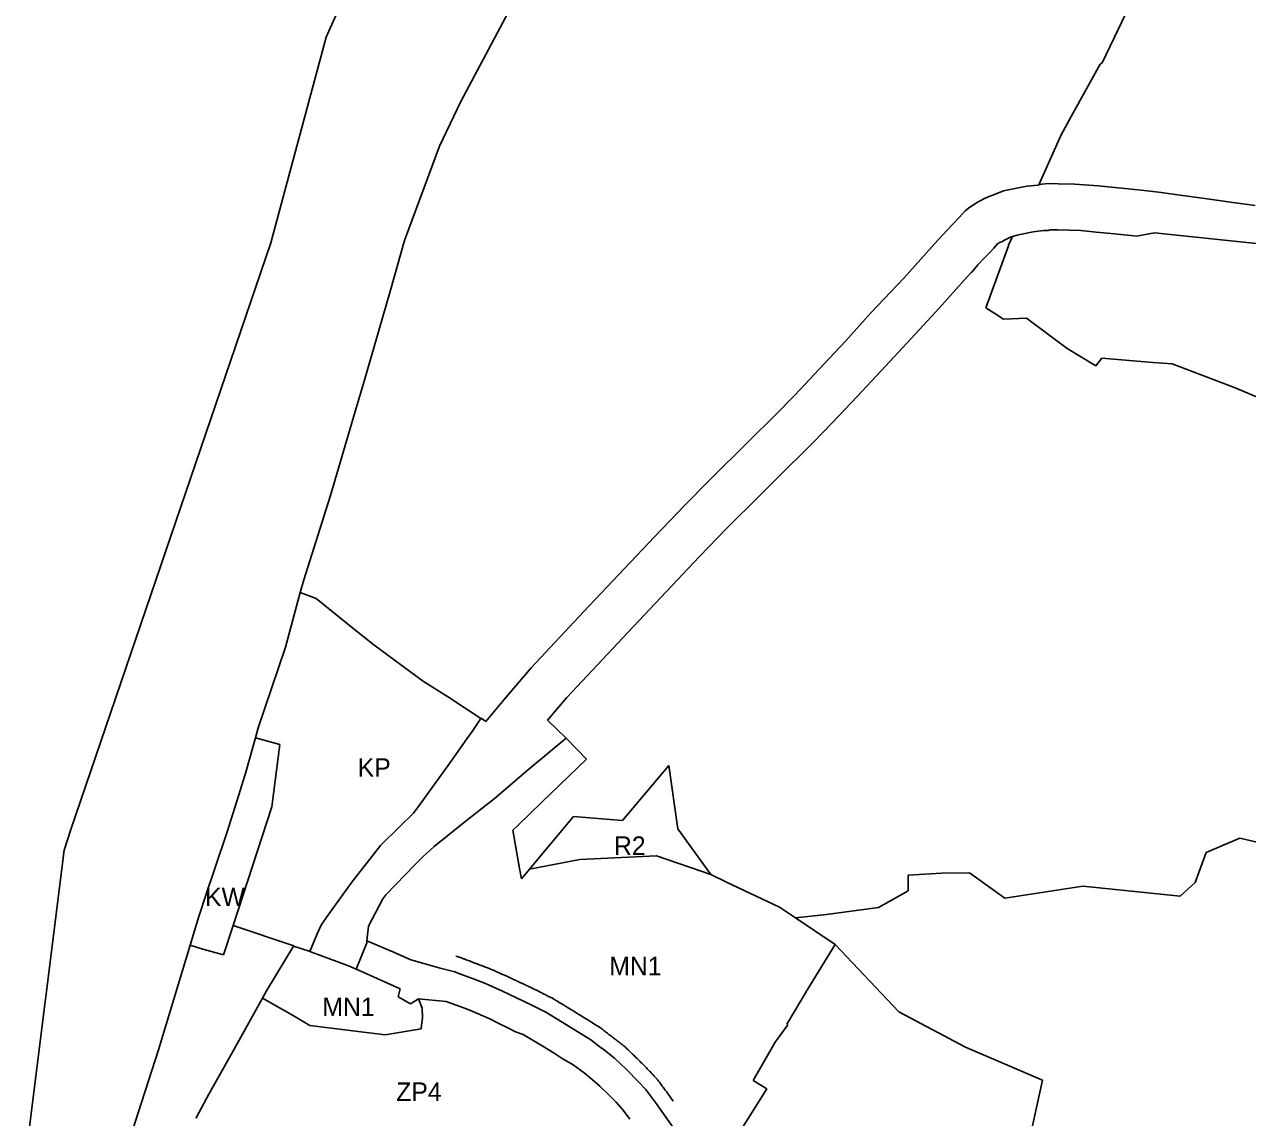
# Model space of a CAD drawing. Extents: x 7413438 to 7416393, y 5541665 to 5544118.
# Drawn here: x 7414058.8 to 7414455.4, y 5543282 to 5543636.5 of the extents above; entities that cross this region are included whole.
import ezdxf

# ---------------------------------------------------------------- set-up
doc = ezdxf.new("R2010")
doc.units = 0
for name, color, linetype in [('linie_rozgraniczajace', 7, 'Continuous'), ('linie_zabudowy_nieprzekraczalne', 7, 'Continuous'), ('oznaczenia_przeznaczen', 7, 'Continuous')]:
    doc.layers.add(name, color=color, linetype=linetype)

msp = doc.modelspace()

# ---------------------------------------------------------------- linework, layer by layer
at = {"layer": 'linie_rozgraniczajace'}
for p, q in [((7414156.63, 5543632.35), (7414203.36, 5543738.15)), ((7414423.99, 5543656.83), (7414408.2, 5543624.04)), ((7414220.77, 5543650.15), (7414200.34, 5543611.48)), ((7414138.74, 5543565.69), (7414156.63, 5543632.35)), ((7414407.58, 5543623.65), (7414398.23, 5543606.68)), ((7414408.2, 5543624.04), (7414407.58, 5543623.65)), ((7414200.34, 5543611.48), (7414193.34, 5543597.07)), ((7414398.23, 5543606.68), (7414394.97, 5543600.71)), ((7414394.97, 5543600.71), (7414387.68, 5543584.53)), ((7414193.34, 5543597.07), (7414182.06, 5543566.46)), ((7414380.6, 5543583.43), (7414376.29, 5543582.54)), ((7414383.79, 5543584.09), (7414380.6, 5543583.43)), ((7414387.64, 5543584.44), (7414383.79, 5543584.09)), ((7414387.68, 5543584.53), (7414387.64, 5543584.44)), ((7414387.68, 5543584.53), (7414387.69, 5543584.49)), ((7414387.69, 5543584.49), (7414388.73, 5543584.76)), ((7414388.73, 5543584.76), (7414390.91, 5543584.95)), ((7414390.91, 5543584.95), (7414393.95, 5543584.87)), ((7414393.95, 5543584.87), (7414399.43, 5543584.71)), ((7414399.43, 5543584.71), (7414406.96, 5543584.2)), ((7414406.96, 5543584.2), (7414413.4, 5543583.54)), ((7414413.4, 5543583.54), (7414420.86, 5543582.78)), ((7414420.86, 5543582.78), (7414426.64, 5543582.14)), ((7414368.03, 5543578.98), (7414365.32, 5543577.23)), ((7414370.48, 5543580.34), (7414368.03, 5543578.98)), ((7414374.43, 5543581.84), (7414370.48, 5543580.34)), ((7414376.29, 5543582.54), (7414374.43, 5543581.84)), ((7414426.64, 5543582.14), (7414432.69, 5543581.29)), ((7414432.69, 5543581.29), (7414435.2, 5543580.95)), ((7414435.2, 5543580.95), (7414442.27, 5543579.96)), ((7414442.27, 5543579.96), (7414449.82, 5543578.9)), ((7414449.82, 5543578.9), (7414457.83, 5543577.78)), ((7414363.84, 5543576.04), (7414361.94, 5543574)), ((7414365.32, 5543577.23), (7414363.84, 5543576.04)), ((7414359.67, 5543571.59), (7414354.96, 5543566.51)), ((7414361.94, 5543574), (7414359.67, 5543571.59)), ((7414376.56, 5543566.6), (7414377.66, 5543567.13)), ((7414377.66, 5543567.13), (7414378.57, 5543567.48)), ((7414379.13, 5543567.72), (7414377.91, 5543564.92)), ((7414378.57, 5543567.48), (7414379.13, 5543567.72)), ((7414379.13, 5543567.72), (7414381.16, 5543568.29)), ((7414381.16, 5543568.29), (7414385.86, 5543569.23)), ((7414385.86, 5543569.23), (7414389.2, 5543569.69)), ((7414389.2, 5543569.69), (7414390.74, 5543569.74)), ((7414390.74, 5543569.74), (7414391.34, 5543569.92)), ((7414391.34, 5543569.92), (7414393.91, 5543569.86)), ((7414393.91, 5543569.86), (7414397.71, 5543569.76)), ((7414397.71, 5543569.76), (7414401.32, 5543569.65)), ((7414401.32, 5543569.65), (7414406.3, 5543569.19)), ((7414406.3, 5543569.19), (7414411.07, 5543568.7)), ((7414411.07, 5543568.7), (7414417.58, 5543568.04)), ((7414417.58, 5543568.04), (7414419.34, 5543567.86)), ((7414419.34, 5543567.86), (7414425.24, 5543568.95)), ((7414425.24, 5543568.95), (7414459.26, 5543565.39)), ((7414073.81, 5543375.42), (7414138.74, 5543565.69)), ((7414182.06, 5543566.46), (7414177.46, 5543550.37)), ((7414354.96, 5543566.51), (7414343.97, 5543554.25)), ((7414377.85, 5543564.75), (7414370.57, 5543544.64)), ((7414371.96, 5543562.71), (7414373.12, 5543563.97)), ((7414373.12, 5543563.97), (7414374.36, 5543565.32)), ((7414374.36, 5543565.32), (7414374.96, 5543565.77)), ((7414374.96, 5543565.77), (7414375.67, 5543566.06)), ((7414375.67, 5543566.06), (7414376.56, 5543566.6)), ((7414377.91, 5543564.92), (7414377.83, 5543564.74)), ((7414377.83, 5543564.74), (7414377.85, 5543564.75)), ((7414367.9, 5543558.52), (7414369.99, 5543560.68)), ((7414369.99, 5543560.68), (7414371.96, 5543562.71)), ((7414363.52, 5543553.56), (7414365.73, 5543556.03)), ((7414365.73, 5543556.03), (7414365.95, 5543556.2)), ((7414365.95, 5543556.2), (7414367.9, 5543558.52)), ((7414343.97, 5543554.25), (7414333.36, 5543543.07)), ((7414355.42, 5543544.53), (7414363.52, 5543553.56)), ((7414177.46, 5543550.37), (7414168.78, 5543520.02)), ((7414333.36, 5543543.07), (7414325.06, 5543533.82)), ((7414345.07, 5543533.29), (7414355.42, 5543544.53)), ((7414370.57, 5543544.64), (7414370.55, 5543544.62)), ((7414370.55, 5543544.62), (7414373.43, 5543542.75)), ((7414373.43, 5543542.75), (7414376.22, 5543540.94)), ((7414376.22, 5543540.94), (7414383.67, 5543541.21)), ((7414383.67, 5543541.21), (7414396.87, 5543531.44)), ((7414325.06, 5543533.82), (7414318.12, 5543526.42)), ((7414336.49, 5543524.11), (7414345.07, 5543533.29)), ((7414396.87, 5543531.44), (7414406.23, 5543525.83)), ((7414406.23, 5543525.83), (7414408.18, 5543528.34)), ((7414408.18, 5543528.34), (7414424.71, 5543526.89)), ((7414318.12, 5543526.42), (7414308.59, 5543516.33)), ((7414328.86, 5543515.91), (7414336.49, 5543524.11)), ((7414424.71, 5543526.89), (7414430.92, 5543526.4)), ((7414430.92, 5543526.4), (7414451.36, 5543518.66)), ((7414168.78, 5543520.02), (7414166.09, 5543510.96)), ((7414308.59, 5543516.33), (7414302.29, 5543509.91)), ((7414322.79, 5543509.51), (7414328.86, 5543515.91)), ((7414451.36, 5543518.66), (7414463.89, 5543513.39)), ((7414166.09, 5543510.96), (7414157.93, 5543483.45)), ((7414302.29, 5543509.91), (7414293.79, 5543501.52)), ((7414318.36, 5543504.83), (7414322.79, 5543509.51)), ((7414313.92, 5543500.26), (7414318.36, 5543504.83)), ((7414293.79, 5543501.52), (7414280.75, 5543488.51)), ((7414309.02, 5543495.4), (7414313.92, 5543500.26)), ((7414308.04, 5543494.57), (7414309.02, 5543495.4)), ((7414297.28, 5543483.71), (7414307.6, 5543494.12)), ((7414307.6, 5543494.12), (7414308.04, 5543494.57)), ((7414280.75, 5543488.51), (7414272.9, 5543480.57)), ((7414286.53, 5543473.13), (7414297.28, 5543483.71)), ((7414157.93, 5543483.45), (7414149.36, 5543456.36)), ((7414272.9, 5543480.57), (7414263.09, 5543470.31)), ((7414277.72, 5543463.94), (7414286.53, 5543473.13)), ((7414263.09, 5543470.31), (7414253.33, 5543460.03)), ((7414268.68, 5543454.41), (7414277.72, 5543463.94)), ((7414253.33, 5543460.03), (7414240.07, 5543446.05)), ((7414149.36, 5543456.36), (7414148.25, 5543452.29)), ((7414148.25, 5543452.29), (7414143.41, 5543434.59)), ((7414148.25, 5543452.29), (7414153.37, 5543450.33)), ((7414254.44, 5543439.33), (7414268.68, 5543454.41)), ((7414153.37, 5543450.33), (7414165.85, 5543440.25)), ((7414240.07, 5543446.05), (7414223.14, 5543427.9)), ((7414165.85, 5543440.25), (7414172.14, 5543435.32)), ((7414234.63, 5543418.24), (7414254.44, 5543439.33)), ((7414143.41, 5543434.59), (7414134.61, 5543408.44)), ((7414172.14, 5543435.32), (7414188.24, 5543423.46)), ((7414223.14, 5543427.9), (7414214.31, 5543417.57)), ((7414188.24, 5543423.46), (7414188.77, 5543423.13)), ((7414188.77, 5543423.13), (7414196.28, 5543418.3)), ((7414196.28, 5543418.3), (7414206.83, 5543411.45)), ((7414214.31, 5543417.57), (7414208.46, 5543410.45)), ((7414228.44, 5543410.9), (7414234.63, 5543418.24)), ((7414134.61, 5543408.44), (7414133.71, 5543405.16)), ((7414206.84, 5543411.38), (7414203.95, 5543407.25)), ((7414206.83, 5543411.45), (7414206.84, 5543411.38)), ((7414206.87, 5543411.44), (7414206.84, 5543411.38)), ((7414206.95, 5543411.55), (7414206.87, 5543411.44)), ((7414208.46, 5543410.45), (7414206.95, 5543411.55)), ((7414234.42, 5543405.07), (7414228.44, 5543410.9)), ((7414133.71, 5543405.16), (7414130.64, 5543394.05)), ((7414141.59, 5543403), (7414133.71, 5543405.16)), ((7414202.27, 5543404.85), (7414196.14, 5543396.09)), ((7414203.95, 5543407.25), (7414202.27, 5543404.85)), ((7414222.34, 5543394.94), (7414234.42, 5543405.07)), ((7414241.09, 5543398.28), (7414234.42, 5543405.07)), ((7414139.01, 5543382.77), (7414141.59, 5543403)), ((7414226.58, 5543384.31), (7414241.09, 5543398.28)), ((7414130.64, 5543394.05), (7414128.32, 5543386.7)), ((7414196.14, 5543396.09), (7414186.79, 5543383.21)), ((7414211.15, 5543385.36), (7414222.34, 5543394.94)), ((7414267.71, 5543396.15), (7414252.71, 5543378.33)), ((7414270.63, 5543375.66), (7414267.71, 5543396.15)), ((7414128.32, 5543386.7), (7414124.43, 5543374.36)), ((7414201.63, 5543377.87), (7414211.15, 5543385.36)), ((7414126.47, 5543344.33), (7414139.01, 5543382.77)), ((7414185, 5543380.74), (7414180.58, 5543376.42)), ((7414186.79, 5543383.21), (7414185, 5543380.74)), ((7414218.74, 5543376.77), (7414226.58, 5543384.31)), ((7414191.66, 5543369.94), (7414201.63, 5543377.87)), ((7414217.13, 5543375.22), (7414218.74, 5543376.77)), ((7414236.83, 5543379.66), (7414222.6, 5543362.57)), ((7414252.71, 5543378.33), (7414236.83, 5543379.66)), ((7414071.65, 5543368.72), (7414073.81, 5543375.42)), ((7414124.43, 5543374.36), (7414117.19, 5543352.83)), ((7414180.58, 5543376.42), (7414174.3, 5543370.2)), ((7414219.38, 5543362.76), (7414217.13, 5543375.22)), ((7414281.32, 5543360.84), (7414270.63, 5543375.66)), ((7414452.94, 5543372.64), (7414442.01, 5543367.96)), ((7414465.51, 5543369.7), (7414452.94, 5543372.64)), ((7414058.82, 5543265.55), (7414071.65, 5543368.72)), ((7414174.3, 5543370.2), (7414164.98, 5543358.38)), ((7414187.96, 5543366.54), (7414191.66, 5543369.94)), ((7414185.55, 5543364.11), (7414187.96, 5543366.54)), ((7414222.6, 5543362.57), (7414238.94, 5543365.68)), ((7414238.94, 5543365.68), (7414263.79, 5543366.89)), ((7414263.79, 5543366.89), (7414281.32, 5543360.84)), ((7414442.01, 5543367.96), (7414438.43, 5543358.28)), ((7414175.94, 5543354.26), (7414185.55, 5543364.11)), ((7414219.98, 5543359.43), (7414219.38, 5543362.76)), ((7414222.6, 5543362.57), (7414219.98, 5543359.43)), ((7414286.48, 5543358.38), (7414281.32, 5543360.84)), ((7414345.4, 5543360.59), (7414345.33, 5543355.56)), ((7414356.22, 5543361.3), (7414345.4, 5543360.59)), ((7414365.22, 5543361.4), (7414356.22, 5543361.3)), ((7414376.68, 5543353.13), (7414365.22, 5543361.4)), ((7414164.98, 5543358.38), (7414157.92, 5543348.56)), ((7414303.66, 5543350.18), (7414286.48, 5543358.38)), ((7414401.94, 5543357.06), (7414376.68, 5543353.13)), ((7414433.58, 5543353.85), (7414401.94, 5543357.06)), ((7414438.43, 5543358.28), (7414433.58, 5543353.85)), ((7414117.19, 5543352.83), (7414115.96, 5543349.17)), ((7414170.33, 5543344.03), (7414175.03, 5543352.96)), ((7414175.03, 5543352.96), (7414175.94, 5543354.26)), ((7414345.33, 5543355.56), (7414335.76, 5543350.14)), ((7414115.96, 5543349.17), (7414115.37, 5543347.21)), ((7414308.78, 5543346.74), (7414303.66, 5543350.18)), ((7414335.76, 5543350.14), (7414318.9, 5543347.87)), ((7414115.37, 5543347.21), (7414112.54, 5543337.89)), ((7414157.92, 5543348.56), (7414155.1, 5543344.63)), ((7414318.9, 5543347.87), (7414308.78, 5543346.74)), ((7414308.78, 5543346.74), (7414321.66, 5543338.08)), ((7414123.34, 5543334.77), (7414126.47, 5543344.33)), ((7414126.47, 5543344.33), (7414146.11, 5543337.66)), ((7414153.78, 5543341.58), (7414151.32, 5543335.88)), ((7414155.1, 5543344.63), (7414153.78, 5543341.58)), ((7414169.88, 5543339.32), (7414170.33, 5543344.03)), ((7414102.25, 5543303.94), (7414112.54, 5543337.89)), ((7414112.54, 5543337.89), (7414116.62, 5543336.66)), ((7414137.3, 5543323.12), (7414146.04, 5543337.54)), ((7414146.11, 5543337.66), (7414146.04, 5543337.54)), ((7414146.04, 5543337.54), (7414151.17, 5543335.94)), ((7414169.82, 5543338.66), (7414166.36, 5543330.1)), ((7414169.88, 5543339.32), (7414169.82, 5543338.66)), ((7414179.02, 5543335.43), (7414169.88, 5543339.32)), ((7414321.66, 5543338.07), (7414312.69, 5543323.51)), ((7414321.66, 5543338.08), (7414321.66, 5543338.07)), ((7414342.29, 5543316.32), (7414321.66, 5543338.07)), ((7414116.62, 5543336.66), (7414123.34, 5543334.77)), ((7414151.17, 5543335.94), (7414151.32, 5543335.88)), ((7414151.32, 5543335.88), (7414163.94, 5543331.17)), ((7414184.15, 5543333.17), (7414179.02, 5543335.43)), ((7414188.27, 5543331.95), (7414184.15, 5543333.17)), ((7414163.94, 5543331.17), (7414166.36, 5543330.1)), ((7414166.36, 5543330.1), (7414168.86, 5543328.99)), ((7414168.86, 5543328.99), (7414180.63, 5543323.79)), ((7414193.63, 5543330.49), (7414188.27, 5543331.95)), ((7414198.38, 5543329.25), (7414193.63, 5543330.49)), ((7414199.16, 5543328.98), (7414198.38, 5543329.25)), ((7414203.45, 5543327.32), (7414199.16, 5543328.98)), ((7414203.76, 5543327.18), (7414203.45, 5543327.32)), ((7414203.82, 5543327.18), (7414203.76, 5543327.18)), ((7414204.08, 5543327.08), (7414203.82, 5543327.18)), ((7414208.32, 5543325.45), (7414204.08, 5543327.08)), ((7414213.86, 5543322.98), (7414208.32, 5543325.45)), ((7414136, 5543320.76), (7414137.3, 5543323.12)), ((7414180.63, 5543323.79), (7414180.04, 5543321.2)), ((7414180.04, 5543321.2), (7414183.97, 5543318.92)), ((7414218.41, 5543320.85), (7414213.86, 5543322.98)), ((7414312.35, 5543322.95), (7414306.26, 5543312.6)), ((7414312.61, 5543323.39), (7414312.35, 5543322.95)), ((7414312.68, 5543323.52), (7414312.61, 5543323.39)), ((7414312.69, 5543323.51), (7414312.68, 5543323.52)), ((7414126.33, 5543303.25), (7414136, 5543320.76)), ((7414136, 5543320.76), (7414145.73, 5543315.15)), ((7414183.97, 5543318.92), (7414186.56, 5543320.5)), ((7414186.56, 5543320.5), (7414186.57, 5543320.45)), ((7414186.57, 5543320.45), (7414195.57, 5543319.65)), ((7414187.76, 5543317.52), (7414186.57, 5543320.45)), ((7414187.86, 5543314.35), (7414187.76, 5543317.52)), ((7414195.57, 5543319.65), (7414201.53, 5543317.44)), ((7414201.53, 5543317.44), (7414203.4, 5543316.75)), ((7414223.29, 5543318.5), (7414218.41, 5543320.85)), ((7414227.84, 5543316.2), (7414223.29, 5543318.5)), ((7414145.73, 5543315.15), (7414151.38, 5543311.89)), ((7414187.58, 5543312), (7414187.86, 5543314.35)), ((7414203.4, 5543316.75), (7414209.75, 5543313.98)), ((7414209.75, 5543313.98), (7414212.46, 5543312.63)), ((7414233.2, 5543312.96), (7414227.84, 5543316.2)), ((7414363.98, 5543304.79), (7414342.29, 5543316.32)), ((7414151.38, 5543311.89), (7414175.73, 5543308.86)), ((7414175.73, 5543308.86), (7414187.44, 5543310.79)), ((7414187.44, 5543310.79), (7414187.58, 5543312)), ((7414212.46, 5543312.63), (7414215.97, 5543310.89)), ((7414215.97, 5543310.89), (7414218, 5543309.83)), ((7414218, 5543309.83), (7414220.47, 5543308.96)), ((7414242.45, 5543307.23), (7414233.2, 5543312.96)), ((7414306.29, 5543312.07), (7414302.26, 5543306.4)), ((7414306.26, 5543312.6), (7414306.05, 5543312.24)), ((7414306.05, 5543312.24), (7414306.3, 5543312.08)), ((7414306.3, 5543312.08), (7414306.29, 5543312.07)), ((7414220.47, 5543308.96), (7414226.72, 5543305.24)), ((7414226.72, 5543305.24), (7414230.53, 5543302.85)), ((7414245.97, 5543304.52), (7414242.45, 5543307.23)), ((7414302.26, 5543306.4), (7414295.04, 5543293.97)), ((7414093.48, 5543276.85), (7414102.25, 5543303.94)), ((7414118.59, 5543289.58), (7414126.33, 5543303.25)), ((7414230.53, 5543302.85), (7414233.16, 5543301.2)), ((7414233.16, 5543301.2), (7414236.68, 5543299.06)), ((7414245.98, 5543304.52), (7414245.97, 5543304.52)), ((7414246.87, 5543303.83), (7414245.98, 5543304.52)), ((7414250.18, 5543301.27), (7414246.87, 5543303.83)), ((7414254.01, 5543297.62), (7414250.18, 5543301.27)), ((7414388.93, 5543294.07), (7414363.98, 5543304.79)), ((7414236.68, 5543299.06), (7414240.27, 5543296.47)), ((7414257.92, 5543293.63), (7414254.01, 5543297.62)), ((7414240.27, 5543296.47), (7414241.55, 5543295.44)), ((7414241.55, 5543295.44), (7414243.7, 5543293.67)), ((7414243.7, 5543293.67), (7414245.36, 5543292.2)), ((7414260.23, 5543291.16), (7414257.92, 5543293.63)), ((7414295.04, 5543293.97), (7414299.53, 5543291.36)), ((7414379.75, 5543252.21), (7414388.93, 5543294.07)), ((7414114.62, 5543282.17), (7414118.59, 5543289.58)), ((7414245.36, 5543292.2), (7414248.47, 5543289.19)), ((7414248.47, 5543289.19), (7414250.68, 5543286.95)), ((7414263.45, 5543286.83), (7414260.23, 5543291.16)), ((7414299.53, 5543291.36), (7414281.28, 5543262.26)), ((7414250.68, 5543286.95), (7414252.91, 5543284.38)), ((7414269.13, 5543278.72), (7414263.45, 5543286.83)), ((7414114.44, 5543281.83), (7414114.62, 5543282.17)), ((7414252.91, 5543284.38), (7414255.07, 5543281.52))]:
    msp.add_line(p, q, dxfattribs=at)
at = {"layer": 'linie_zabudowy_nieprzekraczalne'}
msp.add_open_spline([(7414198.64, 5543334.33), (7414199.49, 5543334.11), (7414199.73, 5543334.04), (7414199.83, 5543334.01), (7414199.98, 5543333.96), (7414200.23, 5543333.88), (7414200.51, 5543333.78), (7414200.7, 5543333.72), (7414200.79, 5543333.68), (7414200.85, 5543333.66), (7414201.11, 5543333.56), (7414201.99, 5543333.22), (7414203.45, 5543332.66), (7414204.69, 5543332.18), (7414205.2, 5543331.98), (7414205.3, 5543331.94), (7414205.34, 5543331.93), (7414205.38, 5543331.91), (7414205.43, 5543331.9), (7414205.47, 5543331.88), (7414205.55, 5543331.85), (7414205.99, 5543331.68), (7414207.19, 5543331.22), (7414208.75, 5543330.61), (7414209.82, 5543330.2), (7414210.2, 5543330.05), (7414210.28, 5543330.02), (7414210.55, 5543329.9), (7414211.61, 5543329.43), (7414213.46, 5543328.6), (7414215.1, 5543327.87), (7414215.9, 5543327.51), (7414216.67, 5543327.16), (7414218.09, 5543326.49), (7414219.57, 5543325.8), (7414220.39, 5543325.41), (7414221.06, 5543325.09), (7414222.4, 5543324.45), (7414224.07, 5543323.64), (7414225.15, 5543323.12), (7414225.77, 5543322.81), (7414226.83, 5543322.28), (7414228.4, 5543321.49), (7414229.6, 5543320.88), (7414230.05, 5543320.66), (7414230.16, 5543320.6), (7414230.41, 5543320.45), (7414231.31, 5543319.9), (7414233.05, 5543318.85), (7414234.76, 5543317.82), (7414235.58, 5543317.32), (7414235.75, 5543317.22), (7414235.84, 5543317.16), (7414236.69, 5543316.63), (7414239.12, 5543315.13), (7414242.3, 5543313.16), (7414244.45, 5543311.83), (7414245.16, 5543311.38), (7414245.3, 5543311.29), (7414245.53, 5543311.12), (7414246.22, 5543310.59), (7414247.38, 5543309.7), (7414248.4, 5543308.92), (7414248.96, 5543308.49), (7414249.66, 5543307.95), (7414250.98, 5543306.92), (7414252.36, 5543305.86), (7414253.08, 5543305.31), (7414253.28, 5543305.15), (7414253.36, 5543305.08), (7414253.45, 5543305), (7414253.54, 5543304.92), (7414253.83, 5543304.65), (7414254.71, 5543303.81), (7414256.03, 5543302.55), (7414257.05, 5543301.57), (7414257.6, 5543301.04), (7414258.36, 5543300.26), (7414259.66, 5543298.94), (7414260.85, 5543297.72), (7414261.38, 5543297.18), (7414261.48, 5543297.08), (7414261.53, 5543297.03), (7414261.8, 5543296.74), (7414262.46, 5543296.03), (7414263.26, 5543295.18), (7414263.77, 5543294.62), (7414263.97, 5543294.4), (7414264.06, 5543294.29), (7414264.32, 5543293.94), (7414265.06, 5543292.96), (7414266.17, 5543291.47), (7414267.05, 5543290.28), (7414267.39, 5543289.83), (7414267.45, 5543289.75), (7414269.15, 5543287.31)], degree=3, dxfattribs=at)

# ---------------------------------------------------------------- texts
at = {"layer": 'oznaczenia_przeznaczen'}
for s, p in [('KP', (7414166.88, 5543392.52)), ('R2', (7414249.97, 5543367.18)), ('KW', (7414117.38, 5543350.56)), ('MN1', (7414248.44, 5543328.13)), ('MN1', (7414155.42, 5543314.89)), ('ZP4', (7414179.36, 5543287.38))]:
    msp.add_text(s, height=6, dxfattribs=at).set_placement(p)

doc.saveas('drawing.dxf')
